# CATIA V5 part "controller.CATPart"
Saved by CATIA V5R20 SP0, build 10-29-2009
Part number: Part1
Bounding box of the stored display mesh (mm): x -60 to 60, y -59.99 to 59.99, z 0 to 63.997
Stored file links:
  \\cdl-main\htdocs\CLA\2013\INE328\files\temp\controller.CATPart
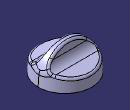
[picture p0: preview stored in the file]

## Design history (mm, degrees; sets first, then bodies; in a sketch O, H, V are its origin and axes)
Body1 (main body)
  Sketch1 on xy-plane, origin (0, 0, 0), H (1, 0, 0), V (0, 1, 0)
    circle A1 centre (0, 0) radius 60
    radius A1 = 60
  Pad1: profile Sketch1, direction (0, 0, 1), length 95
  Draft1: PullDir xy-plane, Angle 4, SupportToDraft face of Pad1 from Sketch1.A1, Neutral start face of Pad1
  Sketch2 on zx-plane, origin (0, 0, 0), H (-1, 0, 0), V (0, 0, 1)
    circle A1 centre (0, 0) radius 64
    radius A1 = 64
  Pocket1: profile Sketch2, direction (0, -1, 0), length 95, mirrored extent, outer side
  Sketch3 on yz-plane, origin (0, 0, 0), H (0, 1, 0), V (0, 0, 1)
    line L1 (75.2682, 21.994) -> (12.9661, 33)
    point P1 (75.2682, 21.994)
    point P2 (12.9661, 33)
    line L2 (12.9661, 33) -> (7.5, 64)
    line L3 (75.2682, 21.994) -> (51.9838, 90.295)
    point P3 (51.9838, 90.295)
    line L4 (51.9838, 90.295) -> (0, 93.774)
    point P4 (0, 93.774)
    point P5 (51.9838, 90.295)
    line L5 (7.5, 64) -> (0, 64)
    point P6 (7.5, 64)
    point P7 (0, 64)
    point P8 (-75.2682, 21.994)
    point P9 (-12.9661, 33)
    point P10 (-51.9838, 90.295)
    point P11 (0, 93.774)
    point P12 (-51.9838, 90.295)
    point P13 (-7.5, 64)
    point P14 (0, 64)
    line L6 (-75.2682, 21.994) -> (-12.9661, 33)
    line L7 (-12.9661, 33) -> (-7.5, 64)
    line L8 (-75.2682, 21.994) -> (-51.9838, 90.295)
    line L9 (-51.9838, 90.295) -> (0, 93.774)
    line L10 (-7.5, 64) -> (0, 64)
    angle L2 L7 = 20
    distance L10 H = 64
    distance P2 H = 33
    distance P13 P14 = 7.5
    coincidence: P4 V, P6 L2, P7 V, P5 P3, P6 L5, P13 L10, P4 P11, P7 P14, P10 P12
    horizontal: L5 H
    symmetry: P1 P8 V, P2 P9 V, P3 P10 V, P4 P11 V, P5 P12 V, P6 P13 V, P7 P14 V, L1 L6 V, L2 L7 V, L3 L8 V, L4 L9 V, L5 L10 V
  Pocket2: profile Sketch3, direction (-1, 0, 0), length 95, mirrored extent
  Fillet1: radius 20, on edge [face of Pocket2 from Sketch3.L7 | face of Pocket2 from Sketch3.L6]; edge [face of Pad1 from Sketch1.A1 | face of Pocket1 from Sketch2.A1] (x2); edge [face of Pocket2 from Sketch3.L1 | face of Pocket2 from Sketch3.L2]
  Fillet2: radius 5, on edge [face of Pocket2 from Sketch3.L6 | face of Pad1 from Sketch1.A1]; edge [face of Pad1 from Sketch1.A1 | face of Pocket2 from Sketch3.L1]
  Shell1: IntOffset 4, Face start face of Pad1, ExtOffset 0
